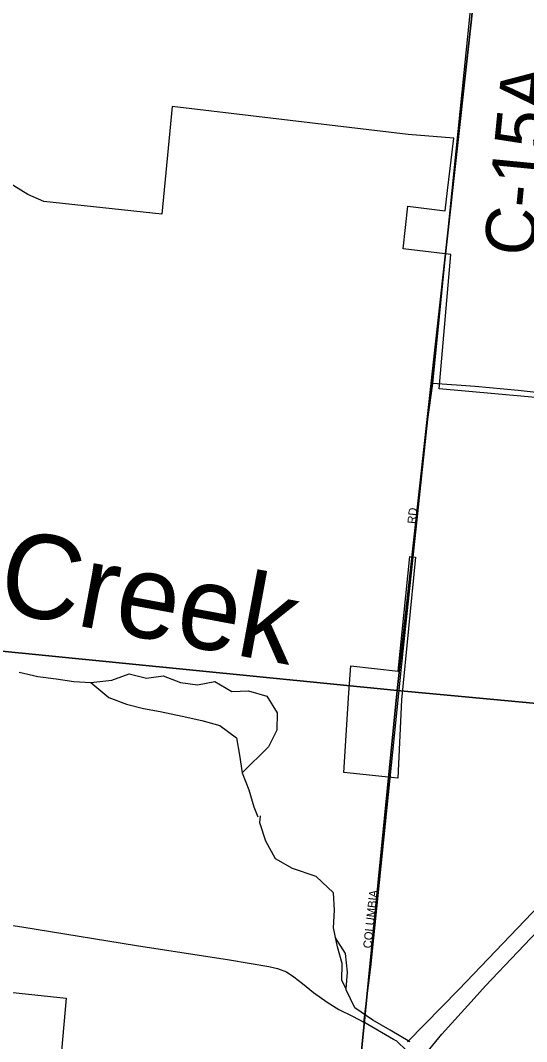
# Model space of a CAD drawing. Extents: x 0 to 34, y -4 to 22.
# Drawn here: x 3.906 to 4.309, y 17.807 to 18.618 of the extents above; entities that cross this region are included whole.
import ezdxf

# ---------------------------------------------------------------- set-up
doc = ezdxf.new("R2010")
doc.units = 0
for name, color, linetype in [('GM_X_City_Street', 7, 'Continuous'), ('GM_X_City_Street_Text', 7, 'Continuous'), ('GM_X_Corporation', 7, 'Continuous'), ('GM_X_County_Road', 7, 'Continuous'), ('GM_X_County_Road_Text', 7, 'Continuous'), ('GM_X_Interstate_Route', 7, 'Continuous'), ('GM_X_Minor_River', 7, 'Continuous'), ('GM_X_Minor_River_Text', 7, 'Continuous'), ('GM_X_Section', 7, 'Continuous'), ('GM_X_Township_Road', 7, 'Continuous')]:
    doc.layers.add(name, color=color, linetype=linetype)

msp = doc.modelspace()

# ---------------------------------------------------------------- linework, layer by layer
at = {"layer": 'GM_X_City_Street'}
for points in [[(4.17949, 17.82209), (4.18503, 17.86584), (4.21074, 18.11682), (4.23039, 18.30112), (4.23426, 18.32972), (4.24504, 18.43619)], [(3.82994, 17.90487), (3.84872, 17.90493), (3.86221, 17.90421), (3.8719, 17.90305), (3.90755, 17.89787), (3.99874, 17.88301), (4.07256, 17.8715), (4.10396, 17.86644), (4.11089, 17.86471), (4.11795, 17.86196), (4.12397, 17.858), (4.13072, 17.8527), (4.13948, 17.84571), (4.15044, 17.83787), (4.15964, 17.83213), (4.17047, 17.82686), (4.17949, 17.82209)], [(4.20307, 17.80842), (4.17949, 17.82209)]]:
    msp.add_lwpolyline(points, dxfattribs=at)
at = {"layer": 'GM_X_Corporation'}
for points in [[(4.4667, 18.30495), (4.23929, 18.32541), (4.24863, 18.43205), (4.21092, 18.43668), (4.21447, 18.47049), (4.24425, 18.46684), (4.24594, 18.48288), (4.25099, 18.52462), (4.21472, 18.52738), (4.02703, 18.54986), (4.01892, 18.46427), (3.92504, 18.47413), (3.91241, 18.47976), (3.88766, 18.495)], [(4.21432, 17.80658), (4.25497, 17.84812), (4.3193, 17.91513), (4.33556, 17.86635), (4.34646, 17.84071), (4.37529, 17.80581)], [(3.86781, 17.84903), (3.94271, 17.84116), (3.93458, 17.74833)]]:
    msp.add_lwpolyline(points, dxfattribs=at)
msp.add_lwpolyline([(4.16922, 18.10525), (4.2067, 18.10097), (4.21614, 18.19208), (4.22068, 18.19153), (4.20937, 18.07815), (4.2066, 18.01596), (4.16369, 18.02047), (4.1677, 18.08367)], close=True, dxfattribs=at)
at = {"layer": 'GM_X_County_Road'}
for points in [[(4.24504, 18.43619), (4.27961, 18.77764), (4.28221, 18.79071), (4.28627, 18.79333), (4.30269, 18.7967)], [(4.21347, 17.7997), (4.20568, 17.8069), (4.20307, 17.80842)]]:
    msp.add_lwpolyline(points, dxfattribs=at)
at = {"layer": 'GM_X_Interstate_Route'}
for points in [[(4.26738, 17.84101), (4.27637, 17.85087), (4.32777, 17.90498), (4.32874, 17.90593)], [(3.90901, 17.40434), (4.01628, 17.53701), (4.21832, 17.78414), (4.22347, 17.79043), (4.24153, 17.81265), (4.26738, 17.84101)]]:
    msp.add_lwpolyline(points, dxfattribs=at)
at = {"layer": 'GM_X_Minor_River'}
for points in [[(3.9055, 18.10027), (3.92018, 18.09679), (3.93487, 18.09492), (3.94902, 18.09278), (3.96237, 18.09198), (3.97678, 18.0802), (3.99066, 18.0749), (4.00428, 18.07124), (4.01763, 18.06888), (4.03498, 18.06521), (4.05073, 18.06181), (4.06489, 18.05788), (4.07823, 18.04793), (4.08064, 18.03431), (4.08277, 18.02018), (4.08811, 18.00682), (4.09211, 17.9932), (4.09532, 17.98535)], [(3.96237, 18.09198), (3.97919, 18.09385), (3.9928, 18.09893), (4.00669, 18.09545), (4.02003, 18.09733), (4.03365, 18.09197), (4.04727, 18.0901), (4.06115, 18.09278), (4.0745, 18.08475), (4.08785, 18.08528), (4.10226, 18.08127), (4.11054, 18.06783), (4.11027, 18.05421), (4.1036, 18.04086), (4.08277, 18.02018)], [(4.16542, 17.84863), (4.16191, 17.85524), (4.16218, 17.8686), (4.15847, 17.88197), (4.15528, 17.89693), (4.15608, 17.9111), (4.15529, 17.92473), (4.1415, 17.93782), (4.12267, 17.94424), (4.10915, 17.95199), (4.10146, 17.96589), (4.09692, 17.98059), (4.09746, 17.9861)], [(4.16542, 17.84863), (4.16642, 17.86192), (4.16483, 17.87662), (4.15687, 17.88918)], [(4.21616, 17.80649), (4.20036, 17.81569), (4.18657, 17.8237), (4.17225, 17.83359), (4.16536, 17.84776), (4.16542, 17.84863)]]:
    msp.add_lwpolyline(points, dxfattribs=at)
at = {"layer": 'GM_X_Section'}
for points in [[(3.57306, 18.87377), (4.28514, 18.79907), (4.2059, 18.08556), (3.49733, 18.15618)], [(4.99198, 18.73294), (4.91493, 18.01957), (4.2059, 18.08556), (4.28514, 18.79907)], [(3.49733, 18.15618), (4.2059, 18.08556), (4.13495, 17.36839), (3.44178, 17.43755), (3.42315, 17.43952)]]:
    msp.add_lwpolyline(points, close=True, dxfattribs=at)
msp.add_lwpolyline([(4.13495, 17.36839), (4.2059, 18.08556), (4.91493, 18.01957), (4.8638, 17.55452)], dxfattribs=at)
at = {"layer": 'GM_X_Township_Road'}
msp.add_lwpolyline([(4.46007, 18.31461), (4.45963, 18.33496), (4.46029, 18.35015), (4.45303, 18.35434), (4.42492, 18.35722), (4.41683, 18.35468), (4.41353, 18.34965), (4.41053, 18.3315), (4.4063, 18.31873), (4.39578, 18.31516), (4.37839, 18.31626), (4.33799, 18.32015), (4.30216, 18.32397), (4.26792, 18.32722), (4.23426, 18.32972)], dxfattribs=at)

# ---------------------------------------------------------------- texts
at = {"layer": 'GM_X_City_Street_Text'}
for s, rotation, p in [('RD', 83.99458, (4.22073, 18.2178)), ('COLUMBIA', 83.74624, (4.18553, 17.88047))]:
    msp.add_text(s, height=0.006667, rotation=rotation, dxfattribs=at).set_placement(p)
at = {"layer": 'GM_X_County_Road_Text'}
msp.add_text('C-15A', height=0.04, rotation=84.44025, dxfattribs=at).set_placement((4.31462, 18.42976))
at = {"layer": 'GM_X_Minor_River_Text'}
msp.add_text('Creek', height=0.066664, rotation=349.47881, dxfattribs=at).set_placement((3.88623, 18.14936))

doc.saveas('drawing.dxf')
